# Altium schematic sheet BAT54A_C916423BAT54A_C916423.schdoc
size 127 x 101 mm
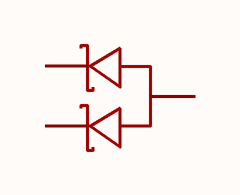
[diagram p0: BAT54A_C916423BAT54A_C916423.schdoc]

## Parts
D?  bat54a_c916423  [SOT-23-3_L2.9-W1.3-P1.90-LS2.4-BR]  (value not drawn)

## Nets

Not connected (* = marked no-connect by the designer): D? 1(K1) 2(K2) 3(A)

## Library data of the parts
D? = bat54a_c916423: 二极管配置:1对共阳极;正向压降(Vf):800mV@100mA;直流反向耐压(Vr):30V;整流电流:200mA;; Manufacturer: JSMSEMI(杰盛微); ManufacturerPart: BAT54A; AddInBom: yes; ModelId: c62791f0466c4ae2a892c056b845b0ca; ModelName: SOT-23-3P_L2.9-W1.3-H1.0-LS2.4-P0.95; ModelTransform: 98.425,114.173,0,180,0,0,0.0005,-0.0005,0; Diode Configuration: 1对共阳极; Voltage - DC Reverse(Vr): 30V; Current - Rectified: 200mA; Reverse Leakage Current (Ir): 2uA@25V; Non-Repetitive Peak Forward Surge Current: 600mA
